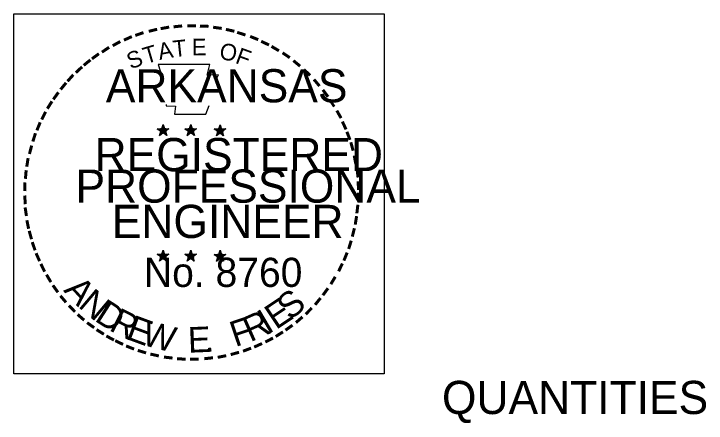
# Model space of a CAD drawing. Extents: x 1226589 to 1228130, y 151309 to 152305.
# Drawn here: x 1227869.5 to 1228130.3, y 151309.4 to 151463.7 of the extents above; entities that cross this region are included whole.
import ezdxf

# ---------------------------------------------------------------- set-up
doc = ezdxf.new("R2010")
doc.units = 0
for name, color, linetype in [('R_Border Notes', 7, 'Continuous'), ('R_Border PE', 7, 'Continuous'), ('R_Border Prem', 7, 'Continuous')]:
    doc.layers.add(name, color=color, linetype=linetype)

msp = doc.modelspace()

# ---------------------------------------------------------------- linework, layer by layer
at = {"layer": 'R_Border PE'}
for p, q in [((1227925.7, 151421.98), (1227925.39, 151420.42)), ((1227925.7, 151421.98), (1227925.45, 151420.36)), ((1227925.7, 151421.98), (1227925.64, 151420.42)), ((1227925.7, 151419.67), (1227925.7, 151421.98)), ((1227925.7, 151421.98), (1227926.14, 151420.36)), ((1227925.7, 151421.98), (1227926.01, 151420.42)), ((1227925.7, 151421.98), (1227925.89, 151420.42)), ((1227936.14, 151421.98), (1227935.82, 151420.42)), ((1227936.14, 151421.98), (1227935.89, 151420.36)), ((1227936.14, 151421.98), (1227936.01, 151420.42)), ((1227936.14, 151419.67), (1227936.14, 151421.98)), ((1227936.14, 151421.98), (1227936.57, 151420.36)), ((1227936.14, 151421.98), (1227936.45, 151420.42)), ((1227936.14, 151421.98), (1227936.26, 151420.42)), ((1227947.2, 151421.86), (1227946.82, 151420.36)), ((1227947.2, 151421.86), (1227946.95, 151420.3)), ((1227947.2, 151421.86), (1227947.07, 151420.3)), ((1227947.2, 151419.61), (1227947.2, 151421.86)), ((1227947.2, 151421.86), (1227947.64, 151420.3)), ((1227947.2, 151421.86), (1227947.51, 151420.3)), ((1227947.2, 151421.86), (1227947.32, 151420.36)), ((1227923.51, 151420.36), (1227925.7, 151419.67)), ((1227923.51, 151420.36), (1227925.14, 151420.23)), ((1227923.51, 151420.36), (1227925.14, 151420.11)), ((1227923.51, 151420.36), (1227925.07, 151419.98)), ((1227923.51, 151420.36), (1227925.07, 151419.73)), ((1227923.51, 151420.36), (1227925.01, 151419.61)), ((1227923.51, 151420.36), (1227925.01, 151419.48)), ((1227924.39, 151417.8), (1227925.7, 151419.67)), ((1227924.39, 151417.8), (1227925.07, 151419.55)), ((1227924.39, 151417.8), (1227925.14, 151419.36)), ((1227924.39, 151417.8), (1227925.26, 151419.3)), ((1227924.39, 151417.8), (1227925.7, 151419.17)), ((1227924.39, 151417.8), (1227925.45, 151419.11)), ((1227927.89, 151420.36), (1227925.7, 151419.67)), ((1227927.07, 151417.8), (1227925.7, 151419.67)), ((1227927.07, 151417.8), (1227925.7, 151419.17)), ((1227927.89, 151420.36), (1227925.95, 151420.23)), ((1227927.07, 151417.8), (1227925.95, 151419.11)), ((1227927.89, 151420.36), (1227926.07, 151420.05)), ((1227927.89, 151420.36), (1227926.07, 151419.92)), ((1227927.07, 151417.8), (1227926.14, 151419.36)), ((1227927.07, 151417.8), (1227926.2, 151419.61)), ((1227927.07, 151417.8), (1227926.32, 151419.67)), ((1227927.89, 151420.36), (1227926.51, 151419.8)), ((1227927.89, 151420.36), (1227926.64, 151419.73)), ((1227927.89, 151420.36), (1227926.7, 151419.67)), ((1227933.95, 151420.36), (1227936.14, 151419.67)), ((1227933.95, 151420.36), (1227935.57, 151420.23)), ((1227933.95, 151420.36), (1227935.57, 151420.11)), ((1227933.95, 151420.36), (1227935.51, 151419.98)), ((1227933.95, 151420.36), (1227935.45, 151419.73)), ((1227933.95, 151420.36), (1227935.45, 151419.61)), ((1227933.95, 151420.36), (1227935.45, 151419.48)), ((1227934.82, 151417.8), (1227936.14, 151419.67)), ((1227934.82, 151417.8), (1227935.51, 151419.55)), ((1227934.82, 151417.8), (1227935.57, 151419.36)), ((1227934.82, 151417.8), (1227935.7, 151419.3)), ((1227934.82, 151417.8), (1227936.14, 151419.17)), ((1227934.82, 151417.8), (1227935.89, 151419.11)), ((1227938.32, 151420.36), (1227936.14, 151419.67)), ((1227937.51, 151417.8), (1227936.14, 151419.67)), ((1227937.51, 151417.8), (1227936.14, 151419.17)), ((1227938.32, 151420.36), (1227936.39, 151420.23)), ((1227937.51, 151417.8), (1227936.39, 151419.11)), ((1227938.32, 151420.36), (1227936.51, 151420.05)), ((1227938.32, 151420.36), (1227936.51, 151419.92)), ((1227937.51, 151417.8), (1227936.57, 151419.36)), ((1227937.51, 151417.8), (1227936.64, 151419.61)), ((1227937.51, 151417.8), (1227936.76, 151419.67)), ((1227938.32, 151420.36), (1227936.95, 151419.8)), ((1227938.32, 151420.36), (1227937.07, 151419.73)), ((1227938.32, 151420.36), (1227937.14, 151419.67)), ((1227945.01, 151420.3), (1227947.2, 151419.61)), ((1227945.01, 151420.3), (1227946.64, 151420.11)), ((1227945.01, 151420.3), (1227946.57, 151419.98)), ((1227945.01, 151420.3), (1227946.57, 151419.92)), ((1227945.01, 151420.3), (1227946.51, 151419.67)), ((1227945.01, 151420.3), (1227946.51, 151419.55)), ((1227945.01, 151420.3), (1227946.51, 151419.42)), ((1227945.82, 151417.73), (1227947.2, 151419.61)), ((1227945.82, 151417.73), (1227946.57, 151419.48)), ((1227945.82, 151417.73), (1227946.64, 151419.3)), ((1227945.82, 151417.73), (1227946.76, 151419.23)), ((1227945.82, 151417.73), (1227947.2, 151419.11)), ((1227949.39, 151420.3), (1227947.2, 151419.61)), ((1227948.51, 151417.73), (1227947.2, 151419.61)), ((1227948.51, 151417.73), (1227947.2, 151419.11)), ((1227949.39, 151420.3), (1227947.45, 151420.17)), ((1227949.39, 151420.3), (1227947.57, 151419.98)), ((1227949.39, 151420.3), (1227947.57, 151419.86)), ((1227948.51, 151417.73), (1227947.64, 151419.3)), ((1227948.51, 151417.73), (1227947.7, 151419.55)), ((1227948.51, 151417.73), (1227947.82, 151419.55)), ((1227949.39, 151420.3), (1227948.01, 151419.73)), ((1227949.39, 151420.3), (1227948.07, 151419.67)), ((1227949.39, 151420.3), (1227948.2, 151419.61)), ((1227924.39, 151417.8), (1227925.76, 151418.98)), ((1227927.07, 151417.8), (1227925.7, 151418.98)), ((1227934.82, 151417.8), (1227936.2, 151418.98)), ((1227937.51, 151417.8), (1227936.14, 151418.98)), ((1227945.82, 151417.73), (1227946.95, 151419.05)), ((1227945.82, 151417.73), (1227947.26, 151418.92)), ((1227948.51, 151417.73), (1227947.2, 151418.92)), ((1227948.51, 151417.73), (1227947.45, 151419.05)), ((1227923.51, 151373.05), (1227925.7, 151372.36)), ((1227923.51, 151373.05), (1227925.14, 151372.86)), ((1227923.51, 151373.05), (1227925.07, 151372.73)), ((1227923.51, 151373.05), (1227925.07, 151372.67)), ((1227923.51, 151373.05), (1227925.01, 151372.42)), ((1227923.51, 151373.05), (1227925.01, 151372.3)), ((1227923.51, 151373.05), (1227925.01, 151372.17)), ((1227924.32, 151370.48), (1227925.7, 151372.36)), ((1227924.32, 151370.48), (1227925.07, 151372.23)), ((1227925.7, 151374.61), (1227925.32, 151373.11)), ((1227925.7, 151374.61), (1227925.45, 151373.05)), ((1227925.7, 151374.61), (1227925.57, 151373.05)), ((1227925.7, 151372.36), (1227925.7, 151374.61)), ((1227925.7, 151374.61), (1227926.14, 151373.05)), ((1227925.7, 151374.61), (1227926.01, 151373.05)), ((1227925.7, 151374.61), (1227925.82, 151373.05)), ((1227927.89, 151373.05), (1227925.7, 151372.36)), ((1227927.01, 151370.48), (1227925.7, 151372.36)), ((1227927.89, 151373.05), (1227925.95, 151372.92)), ((1227927.89, 151373.05), (1227926.07, 151372.73)), ((1227927.89, 151373.05), (1227926.07, 151372.61)), ((1227927.01, 151370.48), (1227926.14, 151372.3)), ((1227927.01, 151370.48), (1227926.32, 151372.3)), ((1227927.89, 151373.05), (1227926.45, 151372.48)), ((1227927.89, 151373.05), (1227926.57, 151372.42)), ((1227927.89, 151373.05), (1227926.7, 151372.3)), ((1227933.95, 151373.05), (1227936.14, 151372.36)), ((1227933.95, 151373.05), (1227935.51, 151372.86)), ((1227933.95, 151373.05), (1227935.51, 151372.73)), ((1227933.95, 151373.05), (1227935.51, 151372.67)), ((1227933.95, 151373.05), (1227935.45, 151372.42)), ((1227933.95, 151373.05), (1227935.45, 151372.3)), ((1227933.95, 151373.05), (1227935.45, 151372.17)), ((1227934.76, 151370.48), (1227936.14, 151372.36)), ((1227934.76, 151370.48), (1227935.51, 151372.23)), ((1227936.14, 151374.61), (1227935.76, 151373.11)), ((1227936.14, 151374.61), (1227935.89, 151373.05)), ((1227936.14, 151374.61), (1227936.01, 151373.05)), ((1227936.14, 151372.36), (1227936.14, 151374.61)), ((1227936.14, 151374.61), (1227936.51, 151373.05)), ((1227936.14, 151374.61), (1227936.45, 151373.05)), ((1227936.14, 151374.61), (1227936.26, 151373.05)), ((1227938.26, 151373.05), (1227936.14, 151372.36)), ((1227937.45, 151370.48), (1227936.14, 151372.36)), ((1227938.26, 151373.05), (1227936.39, 151372.92)), ((1227938.26, 151373.05), (1227936.51, 151372.73)), ((1227938.26, 151373.05), (1227936.51, 151372.61)), ((1227937.45, 151370.48), (1227936.57, 151372.3)), ((1227937.45, 151370.48), (1227936.76, 151372.3)), ((1227938.26, 151373.05), (1227936.89, 151372.48)), ((1227938.26, 151373.05), (1227937.01, 151372.42)), ((1227938.26, 151373.05), (1227937.14, 151372.3)), ((1227945.01, 151372.98), (1227947.2, 151372.3)), ((1227945.01, 151372.98), (1227946.57, 151372.8)), ((1227945.01, 151372.98), (1227946.57, 151372.67)), ((1227945.01, 151372.98), (1227946.51, 151372.55)), ((1227945.01, 151372.98), (1227946.51, 151372.36)), ((1227945.01, 151372.98), (1227946.45, 151372.17)), ((1227945.01, 151372.98), (1227946.45, 151372.05)), ((1227945.82, 151370.42), (1227947.2, 151372.3)), ((1227945.82, 151370.42), (1227946.51, 151372.17)), ((1227947.2, 151374.55), (1227946.82, 151372.98)), ((1227947.2, 151374.55), (1227946.95, 151372.98)), ((1227947.2, 151374.55), (1227947.07, 151372.98)), ((1227947.2, 151372.3), (1227947.2, 151374.55)), ((1227947.2, 151374.55), (1227947.57, 151372.98)), ((1227947.2, 151374.55), (1227947.51, 151372.98)), ((1227947.2, 151374.55), (1227947.32, 151372.98)), ((1227949.32, 151372.98), (1227947.2, 151372.3)), ((1227948.51, 151370.42), (1227947.2, 151372.3)), ((1227949.32, 151372.98), (1227947.45, 151372.86)), ((1227949.32, 151372.98), (1227947.57, 151372.67)), ((1227949.32, 151372.98), (1227947.57, 151372.55)), ((1227948.51, 151370.42), (1227947.64, 151372.23)), ((1227948.51, 151370.42), (1227947.76, 151372.23)), ((1227949.32, 151372.98), (1227947.95, 151372.42)), ((1227949.32, 151372.98), (1227948.07, 151372.3)), ((1227949.32, 151372.98), (1227948.14, 151372.23)), ((1227924.32, 151370.48), (1227925.14, 151371.98)), ((1227924.32, 151370.48), (1227925.26, 151371.92)), ((1227924.32, 151370.48), (1227925.7, 151371.86)), ((1227924.32, 151370.48), (1227925.45, 151371.8)), ((1227924.32, 151370.48), (1227925.7, 151371.67)), ((1227927.01, 151370.48), (1227925.64, 151371.67)), ((1227927.01, 151370.48), (1227925.7, 151371.8)), ((1227927.01, 151370.48), (1227925.89, 151371.8)), ((1227927.01, 151370.48), (1227926.14, 151372.05)), ((1227934.76, 151370.48), (1227935.57, 151371.98)), ((1227934.76, 151370.48), (1227935.7, 151371.92)), ((1227934.76, 151370.48), (1227936.14, 151371.86)), ((1227934.76, 151370.48), (1227935.89, 151371.8)), ((1227934.76, 151370.48), (1227936.14, 151371.67)), ((1227937.45, 151370.48), (1227936.07, 151371.67)), ((1227937.45, 151370.48), (1227936.14, 151371.8)), ((1227937.45, 151370.48), (1227936.32, 151371.8)), ((1227937.45, 151370.48), (1227936.57, 151372.05)), ((1227945.82, 151370.42), (1227946.57, 151371.92)), ((1227945.82, 151370.42), (1227946.76, 151371.86)), ((1227945.82, 151370.42), (1227946.95, 151371.73)), ((1227945.82, 151370.42), (1227947.14, 151371.73)), ((1227945.82, 151370.42), (1227947.2, 151371.61)), ((1227948.51, 151370.42), (1227947.14, 151371.73)), ((1227948.51, 151370.42), (1227947.14, 151371.55)), ((1227948.51, 151370.42), (1227947.39, 151371.73)), ((1227948.51, 151370.42), (1227947.57, 151371.92))]:
    msp.add_line(p, q, dxfattribs=at)
for points in [[(1227923.82, 151444.61), (1227925.45, 151439.42)], [(1227945.76, 151438.86), (1227946.64, 151440.61), (1227942.32, 151440.48), (1227943.26, 151444.61), (1227923.82, 151444.61)], [(1227926.89, 151429.48), (1227926.89, 151428.92), (1227930.39, 151428.8), (1227930.07, 151425.86), (1227941.76, 151425.86), (1227943.01, 151429.17)], [(1227925.7, 151421.98), (1227927.07, 151417.8), (1227923.51, 151420.36), (1227927.89, 151420.36), (1227924.39, 151417.8), (1227925.7, 151421.98)], [(1227936.14, 151421.98), (1227937.51, 151417.8), (1227933.95, 151420.36), (1227938.32, 151420.36), (1227934.82, 151417.8), (1227936.14, 151421.98)], [(1227947.2, 151421.86), (1227948.51, 151417.73), (1227945.01, 151420.3), (1227949.39, 151420.3), (1227945.82, 151417.73), (1227947.2, 151421.86)], [(1227925.7, 151374.61), (1227927.01, 151370.48), (1227923.51, 151373.05), (1227927.89, 151373.05), (1227924.32, 151370.48), (1227925.7, 151374.61)], [(1227936.14, 151374.61), (1227937.45, 151370.48), (1227933.95, 151373.05), (1227938.26, 151373.05), (1227934.76, 151370.48), (1227936.14, 151374.61)], [(1227947.2, 151374.55), (1227948.51, 151370.42), (1227945.01, 151372.98), (1227949.32, 151372.98), (1227945.82, 151370.42), (1227947.2, 151374.55)]]:
    msp.add_lwpolyline(points, dxfattribs=at)
for centre, radius in [((1227925.72, 151419.67), 1.08), ((1227925.72, 151419.67), 0.975), ((1227925.72, 151419.67), 0.904), ((1227925.72, 151419.67), 0.83), ((1227925.72, 151419.67), 0.723), ((1227925.72, 151419.67), 0.672), ((1227925.72, 151419.67), 0.619), ((1227925.72, 151419.67), 0.533), ((1227925.72, 151419.67), 0.467), ((1227925.72, 151419.67), 0.388), ((1227925.72, 151419.67), 0.31), ((1227925.72, 151419.67), 0.231), ((1227925.72, 151419.67), 0.185), ((1227925.72, 151419.67), 0.0901), ((1227936.15, 151419.67), 1.08), ((1227936.15, 151419.67), 0.975), ((1227936.15, 151419.67), 0.904), ((1227936.15, 151419.67), 0.83), ((1227936.15, 151419.67), 0.723), ((1227936.15, 151419.67), 0.672), ((1227936.15, 151419.67), 0.619), ((1227936.15, 151419.67), 0.533), ((1227936.15, 151419.67), 0.467), ((1227936.15, 151419.67), 0.388), ((1227936.15, 151419.67), 0.31), ((1227936.15, 151419.67), 0.231), ((1227936.15, 151419.67), 0.185), ((1227936.15, 151419.67), 0.0901), ((1227947.19, 151419.59), 1.08), ((1227947.19, 151419.59), 0.975), ((1227947.19, 151419.59), 0.904), ((1227947.19, 151419.59), 0.83), ((1227947.19, 151419.59), 0.723), ((1227947.19, 151419.59), 0.672), ((1227947.19, 151419.59), 0.619), ((1227947.19, 151419.59), 0.533), ((1227947.19, 151419.59), 0.467), ((1227947.19, 151419.59), 0.388), ((1227947.19, 151419.59), 0.31), ((1227947.19, 151419.59), 0.231), ((1227947.19, 151419.59), 0.185), ((1227947.19, 151419.59), 0.0901), ((1227925.69, 151372.33), 1.08), ((1227925.69, 151372.33), 0.975), ((1227925.69, 151372.33), 0.904), ((1227925.69, 151372.33), 0.83), ((1227925.69, 151372.33), 0.723), ((1227925.69, 151372.33), 0.672), ((1227925.69, 151372.33), 0.619), ((1227925.69, 151372.33), 0.533), ((1227925.69, 151372.33), 0.467), ((1227925.69, 151372.33), 0.388), ((1227925.69, 151372.33), 0.31), ((1227925.69, 151372.33), 0.231), ((1227925.69, 151372.33), 0.185), ((1227925.69, 151372.33), 0.0901), ((1227936.12, 151372.33), 1.08), ((1227936.12, 151372.33), 0.975), ((1227936.12, 151372.33), 0.904), ((1227936.12, 151372.33), 0.83), ((1227936.12, 151372.33), 0.723), ((1227936.12, 151372.33), 0.672), ((1227936.12, 151372.33), 0.619), ((1227936.12, 151372.33), 0.533), ((1227936.12, 151372.33), 0.467), ((1227936.12, 151372.33), 0.388), ((1227936.12, 151372.33), 0.31), ((1227936.12, 151372.33), 0.231), ((1227936.12, 151372.33), 0.185), ((1227936.12, 151372.33), 0.0901), ((1227947.17, 151372.26), 1.08), ((1227947.17, 151372.26), 0.975), ((1227947.17, 151372.26), 0.904), ((1227947.17, 151372.26), 0.83), ((1227947.17, 151372.26), 0.723), ((1227947.17, 151372.26), 0.672), ((1227947.17, 151372.26), 0.619), ((1227947.17, 151372.26), 0.533), ((1227947.17, 151372.26), 0.467), ((1227947.17, 151372.26), 0.388), ((1227947.17, 151372.26), 0.31), ((1227947.17, 151372.26), 0.231), ((1227947.17, 151372.26), 0.185), ((1227947.17, 151372.26), 0.0901)]:
    msp.add_circle(centre, radius, dxfattribs=at)
at = {"layer": 'R_Border Prem'}
msp.add_lwpolyline([(1227869.48, 151463.65), (1228008.98, 151463.65), (1228008.98, 151328.03), (1227869.48, 151328.03)], close=True, dxfattribs=at)

# ---------------------------------------------------------------- texts
at = {"layer": 'R_Border Notes'}
msp.add_text('QUANTITIES', height=12.5, dxfattribs=at).set_placement((1228030.78, 151312.82))
at = {"layer": 'R_Border PE'}
for s, height, rotation, p in [('-', 10, 13.6302, (1227920.64, 151453.17)), ('-', 10, 10.2193, (1227924.89, 151454.17)), ('-', 10, 5.8968, (1227929.45, 151454.86)), ('-', 10, 0.1862, (1227934.26, 151455.3)), ('-', 10, 357.743, (1227938.82, 151455.23)), ('-', 10, 352.1617, (1227943.45, 151454.86)), ('-', 10, 347.2049, (1227947.95, 151454.17)), ('-', 10, 24.3072, (1227912.01, 151449.98)), ('-', 10, 19.1761, (1227915.95, 151451.67)), ('-', 10, 342.3362, (1227951.89, 151453.17)), ('-', 10, 337.8551, (1227956.51, 151451.8)), ('-', 10, 28.7918, (1227908.07, 151447.98)), ('A', 6.25, 11.2132, (1227924.39, 151446.23)), ('T', 6.25, 6.0228, (1227929.7, 151447.3)), ('E', 6.25, 0.8323, (1227936.57, 151447.98)), ('-', 10, 334.1211, (1227960.45, 151450.11)), ('-', 10, 34.0636, (1227904.32, 151445.67)), ('T', 6.25, 16.4036, (1227919.2, 151444.67)), ('O', 6.25, 350.4515, (1227946.64, 151446.67)), ('F', 6.25, 340.0707, (1227952.57, 151445.23)), ('-', 10, 329.6409, (1227964.07, 151448.36)), ('-', 10, 36.2317, (1227900.7, 151443.23)), ('S', 6.25, 21.594, (1227913.51, 151442.61)), ('-', 10, 325.8627, (1227968.07, 151446.11)), ('-', 10, 38.9507, (1227897.76, 151440.86)), ('-', 10, 320.5297, (1227971.89, 151443.42)), ('-', 10, 42.9622, (1227895.01, 151438.23)), ('-', 10, 315.5786, (1227975.64, 151440.36)), ('-', 10, 48.423, (1227892.2, 151435.23)), ('-', 10, 50.6142, (1227889.7, 151432.23)), ('-', 10, 309.8797, (1227979.2, 151436.92)), ('-', 10, 306.6522, (1227982.45, 151433.17)), ('-', 10, 54.2325, (1227887.14, 151428.67)), ('-', 10, 58.0706, (1227885.07, 151425.36)), ('-', 8.75, 303.6753, (1227985.51, 151429.61)), ('-', 10, 62.8713, (1227883.14, 151421.55)), ('-', 10, 299.6684, (1227987.51, 151425.8)), ('-', 10, 67.7743, (1227881.51, 151417.73)), ('-', 10, 294.6628, (1227989.51, 151421.98)), ('-', 10, 290.5728, (1227991.14, 151418.42)), ('-', 10, 72.3945, (1227880.14, 151413.8)), ('-', 10, 75.461, (1227878.95, 151409.3)), ('-', 10, 285.1233, (1227992.57, 151414.8)), ('-', 10, 81.2013, (1227878.07, 151404.86)), ('-', 10, 280.5493, (1227993.82, 151410.11)), ('-', 10, 85.1863, (1227877.64, 151400.55)), ('-', 10, 276.5962, (1227994.89, 151405.36)), ('-', 10, 89.0622, (1227877.45, 151396.17)), ('-', 10, 274.3301, (1227995.26, 151400.8)), ('-', 10, 269.9407, (1227995.45, 151396.86)), ('-', 10, 94.1959, (1227877.7, 151391.61)), ('-', 10, 98.9479, (1227878.14, 151387.48)), ('-', 10, 263.5172, (1227995.32, 151392.73)), ('-', 10, 101.7149, (1227878.95, 151382.86)), ('-', 10, 260.9953, (1227994.89, 151388.61)), ('-', 10, 255.7626, (1227994.2, 151384.36)), ('-', 10, 105.4578, (1227880.01, 151379.17)), ('-', 10, 109.0874, (1227881.32, 151375.23)), ('-', 10, 252.8681, (1227993.07, 151379.86)), ('-', 10, 114.0643, (1227882.95, 151371.48)), ('-', 10, 247.8887, (1227991.7, 151375.67)), ('-', 10, 115.7289, (1227884.82, 151367.61)), ('-', 10, 244.6197, (1227990.01, 151371.73)), ('-', 10, 120.4471, (1227887.07, 151363.98)), ('-', 10, 239.0712, (1227987.57, 151367.05)), ('-', 10, 125.8934, (1227889.57, 151360.48)), ('A', 9.62, 312.4727, (1227887.95, 151359.29)), ('N', 9.62, 319.8362, (1227893.38, 151353.36)), ('S', 9.62, 39.723, (1227973.61, 151347.89)), ('-', 10, 233.8452, (1227985.07, 151362.98)), ('-', 10, 130.7181, (1227892.45, 151356.98)), ('E', 9.62, 33.8878, (1227968.27, 151344.41)), ('-', 10, 231.2538, (1227982.39, 151359.42)), ('-', 10, 134.2238, (1227895.7, 151353.61)), ('D', 9.62, 327.1996, (1227899.53, 151348.17)), ('R', 9.62, 333.1738, (1227904.97, 151344.57)), ('R', 9.62, 24.0235, (1227958.54, 151339.81)), ('I', 9.62, 30.5534, (1227965.07, 151342.67)), ('-', 10, 225.7653, (1227979.39, 151355.92)), ('-', 10, 138.9338, (1227898.95, 151350.73)), ('E', 9.62, 339.7037, (1227911.31, 151341.3)), ('F', 9.62, 18.6051, (1227952.89, 151338.02)), ('-', 10, 221.0851, (1227976.14, 151352.73)), ('-', 10, 144.6463, (1227902.45, 151348.17)), ('W', 9.62, 345.5389, (1227917.26, 151339.01)), ('-', 10, 215.7363, (1227972.7, 151349.8)), ('-', 10, 148.0898, (1227905.95, 151345.86)), ('E', 9.62, 2.2804, (1227935.23, 151335.92)), ('-', 10, 212.2491, (1227969.32, 151347.36)), ('-', 10, 151.5704, (1227909.57, 151343.8)), ('-', 10, 154.6002, (1227912.82, 151342.3)), ('-', 10, 207.3568, (1227965.89, 151345.17)), ('-', 10, 158.5612, (1227916.76, 151340.67)), ('-', 10, 204.2516, (1227961.95, 151343.17)), ('-', 10, 162.7983, (1227921.01, 151339.36)), ('-', 10, 167.5555, (1227925.51, 151338.36)), ('.', 9.62, 8.1156, (1227941.61, 151336.09)), ('-', 10, 195.4743, (1227953.89, 151339.98)), ('-', 10, 200.7184, (1227958.07, 151341.48)), ('-', 10, 173.1155, (1227930.32, 151337.67)), ('-', 10, 176.5183, (1227935.01, 151337.3)), ('-', 10, 181.5918, (1227939.64, 151337.42)), ('-', 10, 185.8167, (1227944.7, 151337.92)), ('-', 10, 191.2858, (1227949.32, 151338.73))]:
    msp.add_text(s, height=height, rotation=rotation, dxfattribs=at).set_placement(p)
for s, height, p in [('ARKANSAS', 12.5, (1227904.14, 151430.3)), ('REGISTERED', 12.5, (1227899.89, 151404.36)), ('PROFESSIONAL', 12.4999, (1227892.7, 151392.48)), ('ENGINEER', 12.5, (1227906.39, 151379.17)), ('No. 8760', 11, (1227918.5, 151360.73))]:
    msp.add_text(s, height=height, dxfattribs=at).set_placement(p)

doc.saveas('drawing.dxf')
